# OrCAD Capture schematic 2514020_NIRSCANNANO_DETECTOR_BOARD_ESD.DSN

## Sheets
1 PAGE-01  TITLE: title: ESD, Mobile Spectroscopy Detector Board
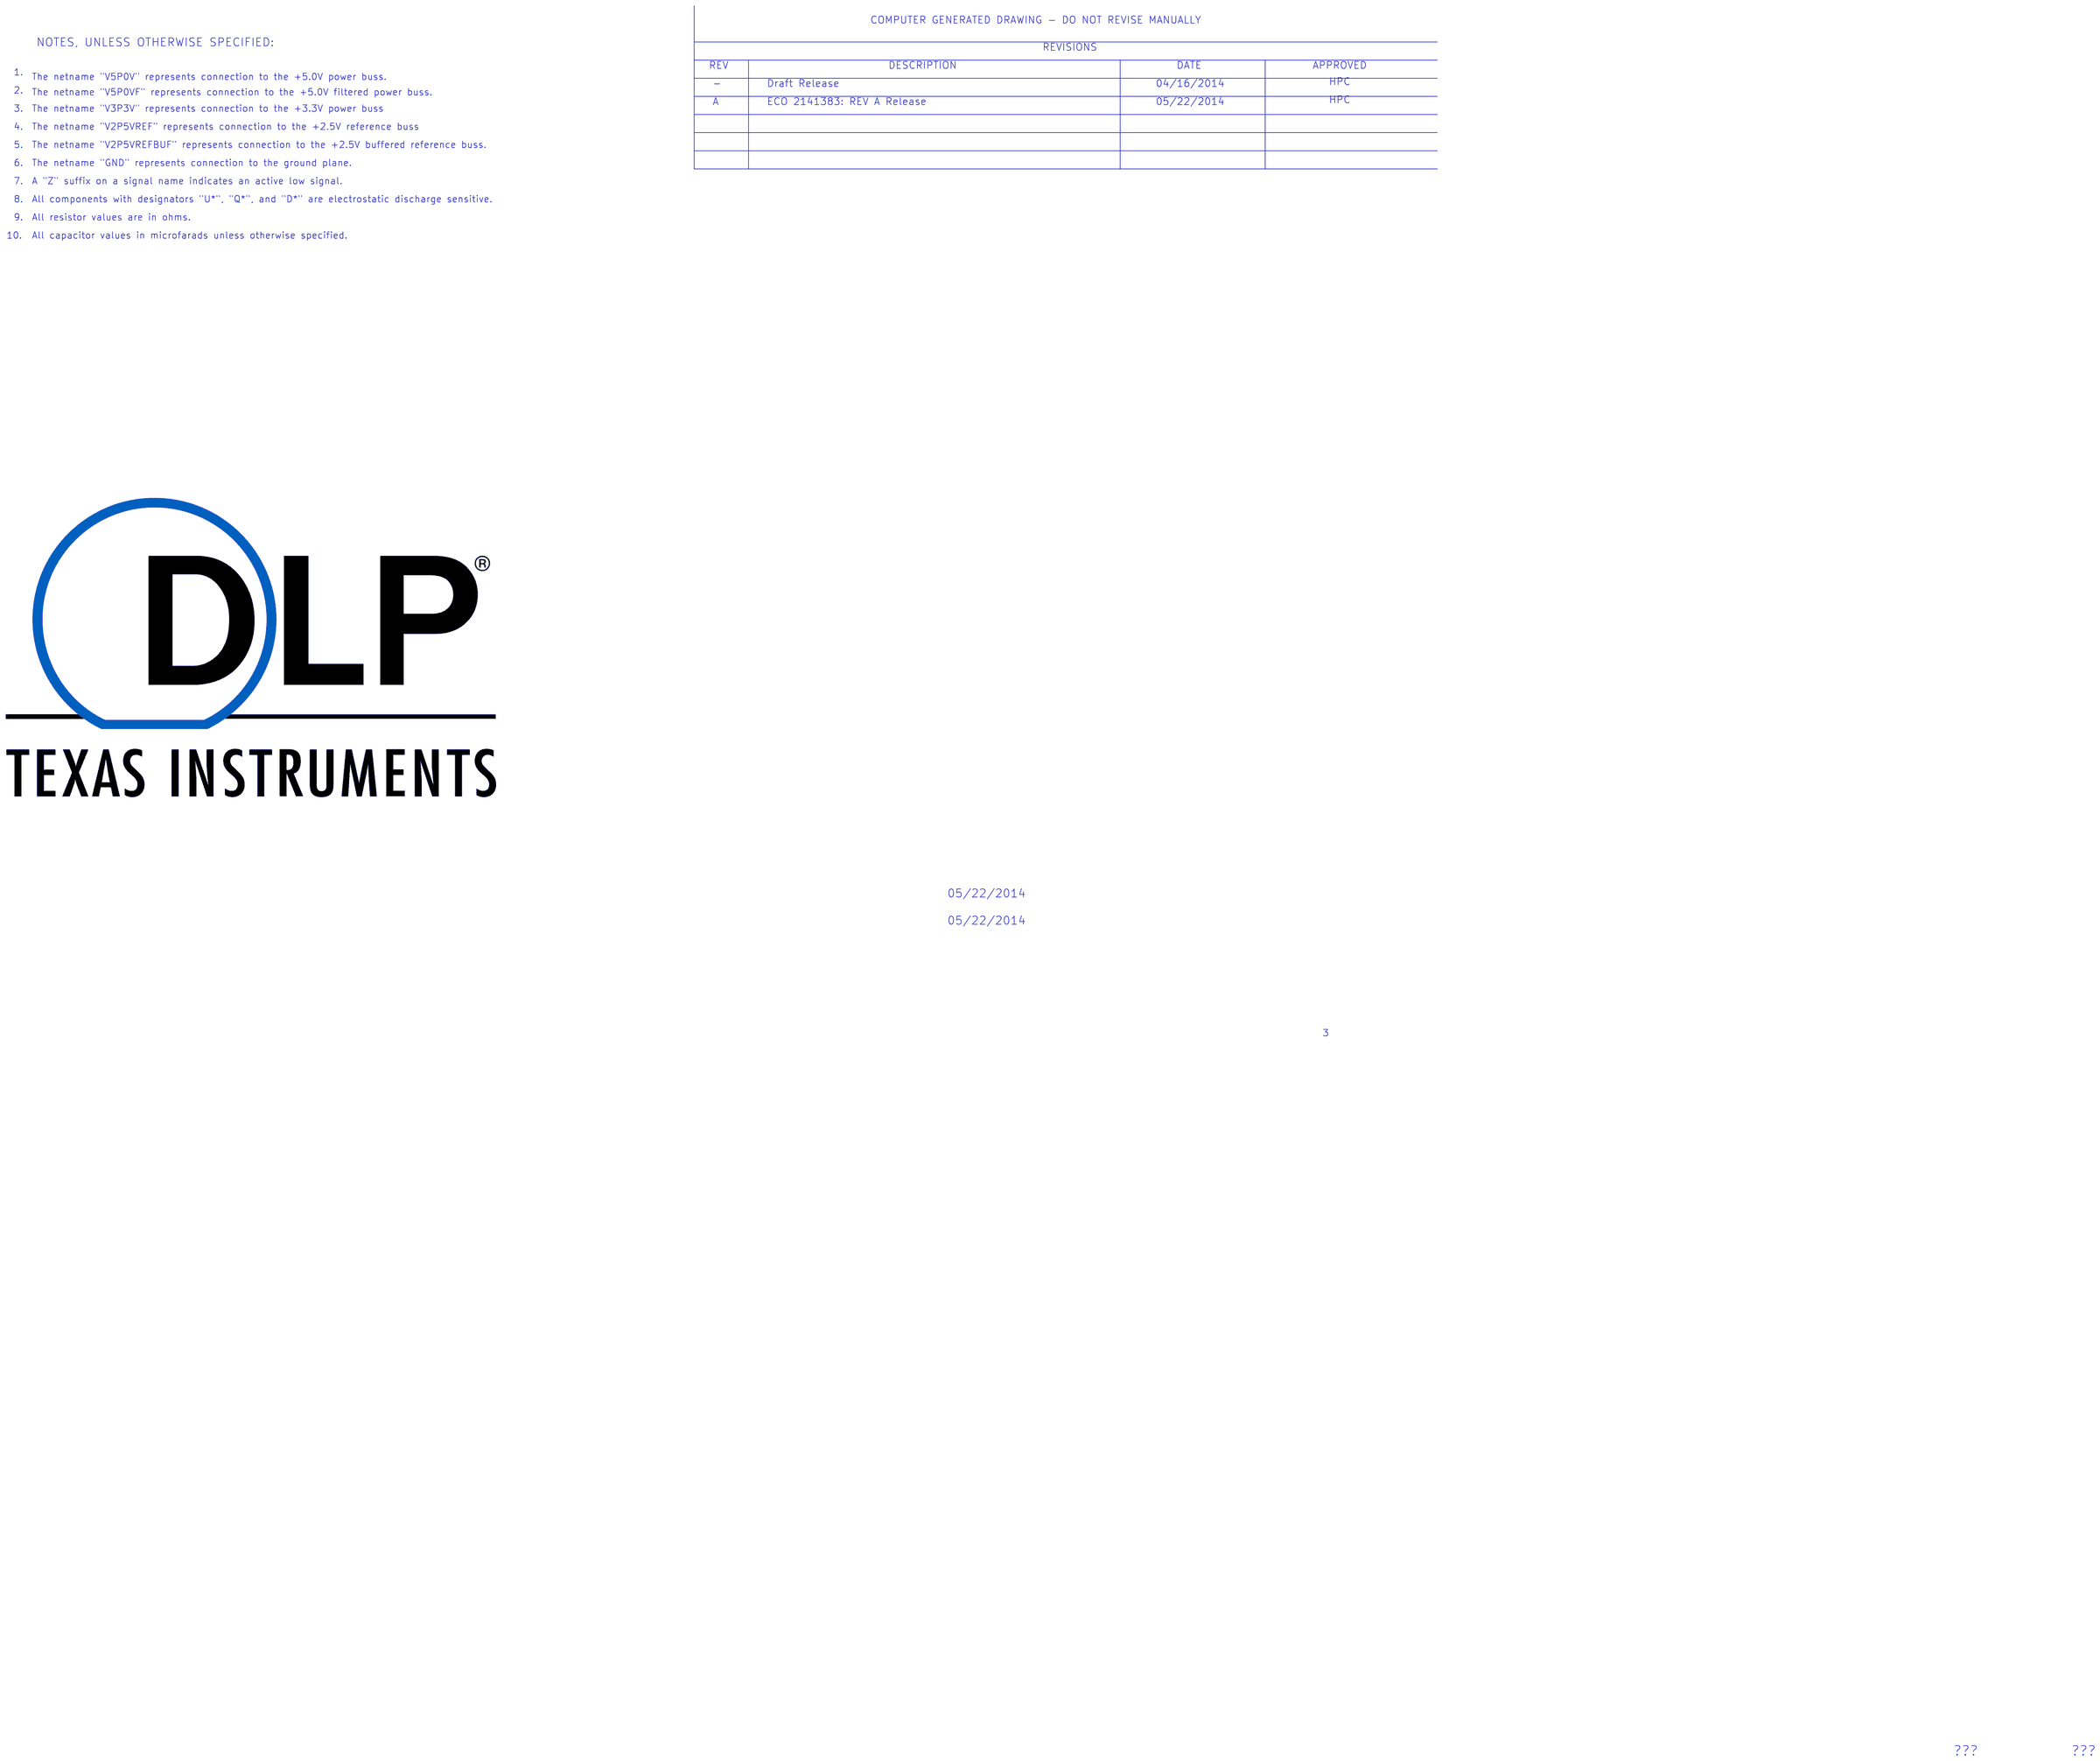
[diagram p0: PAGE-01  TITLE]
2 PAGE-02  Detector Amp ADS1255: size A3
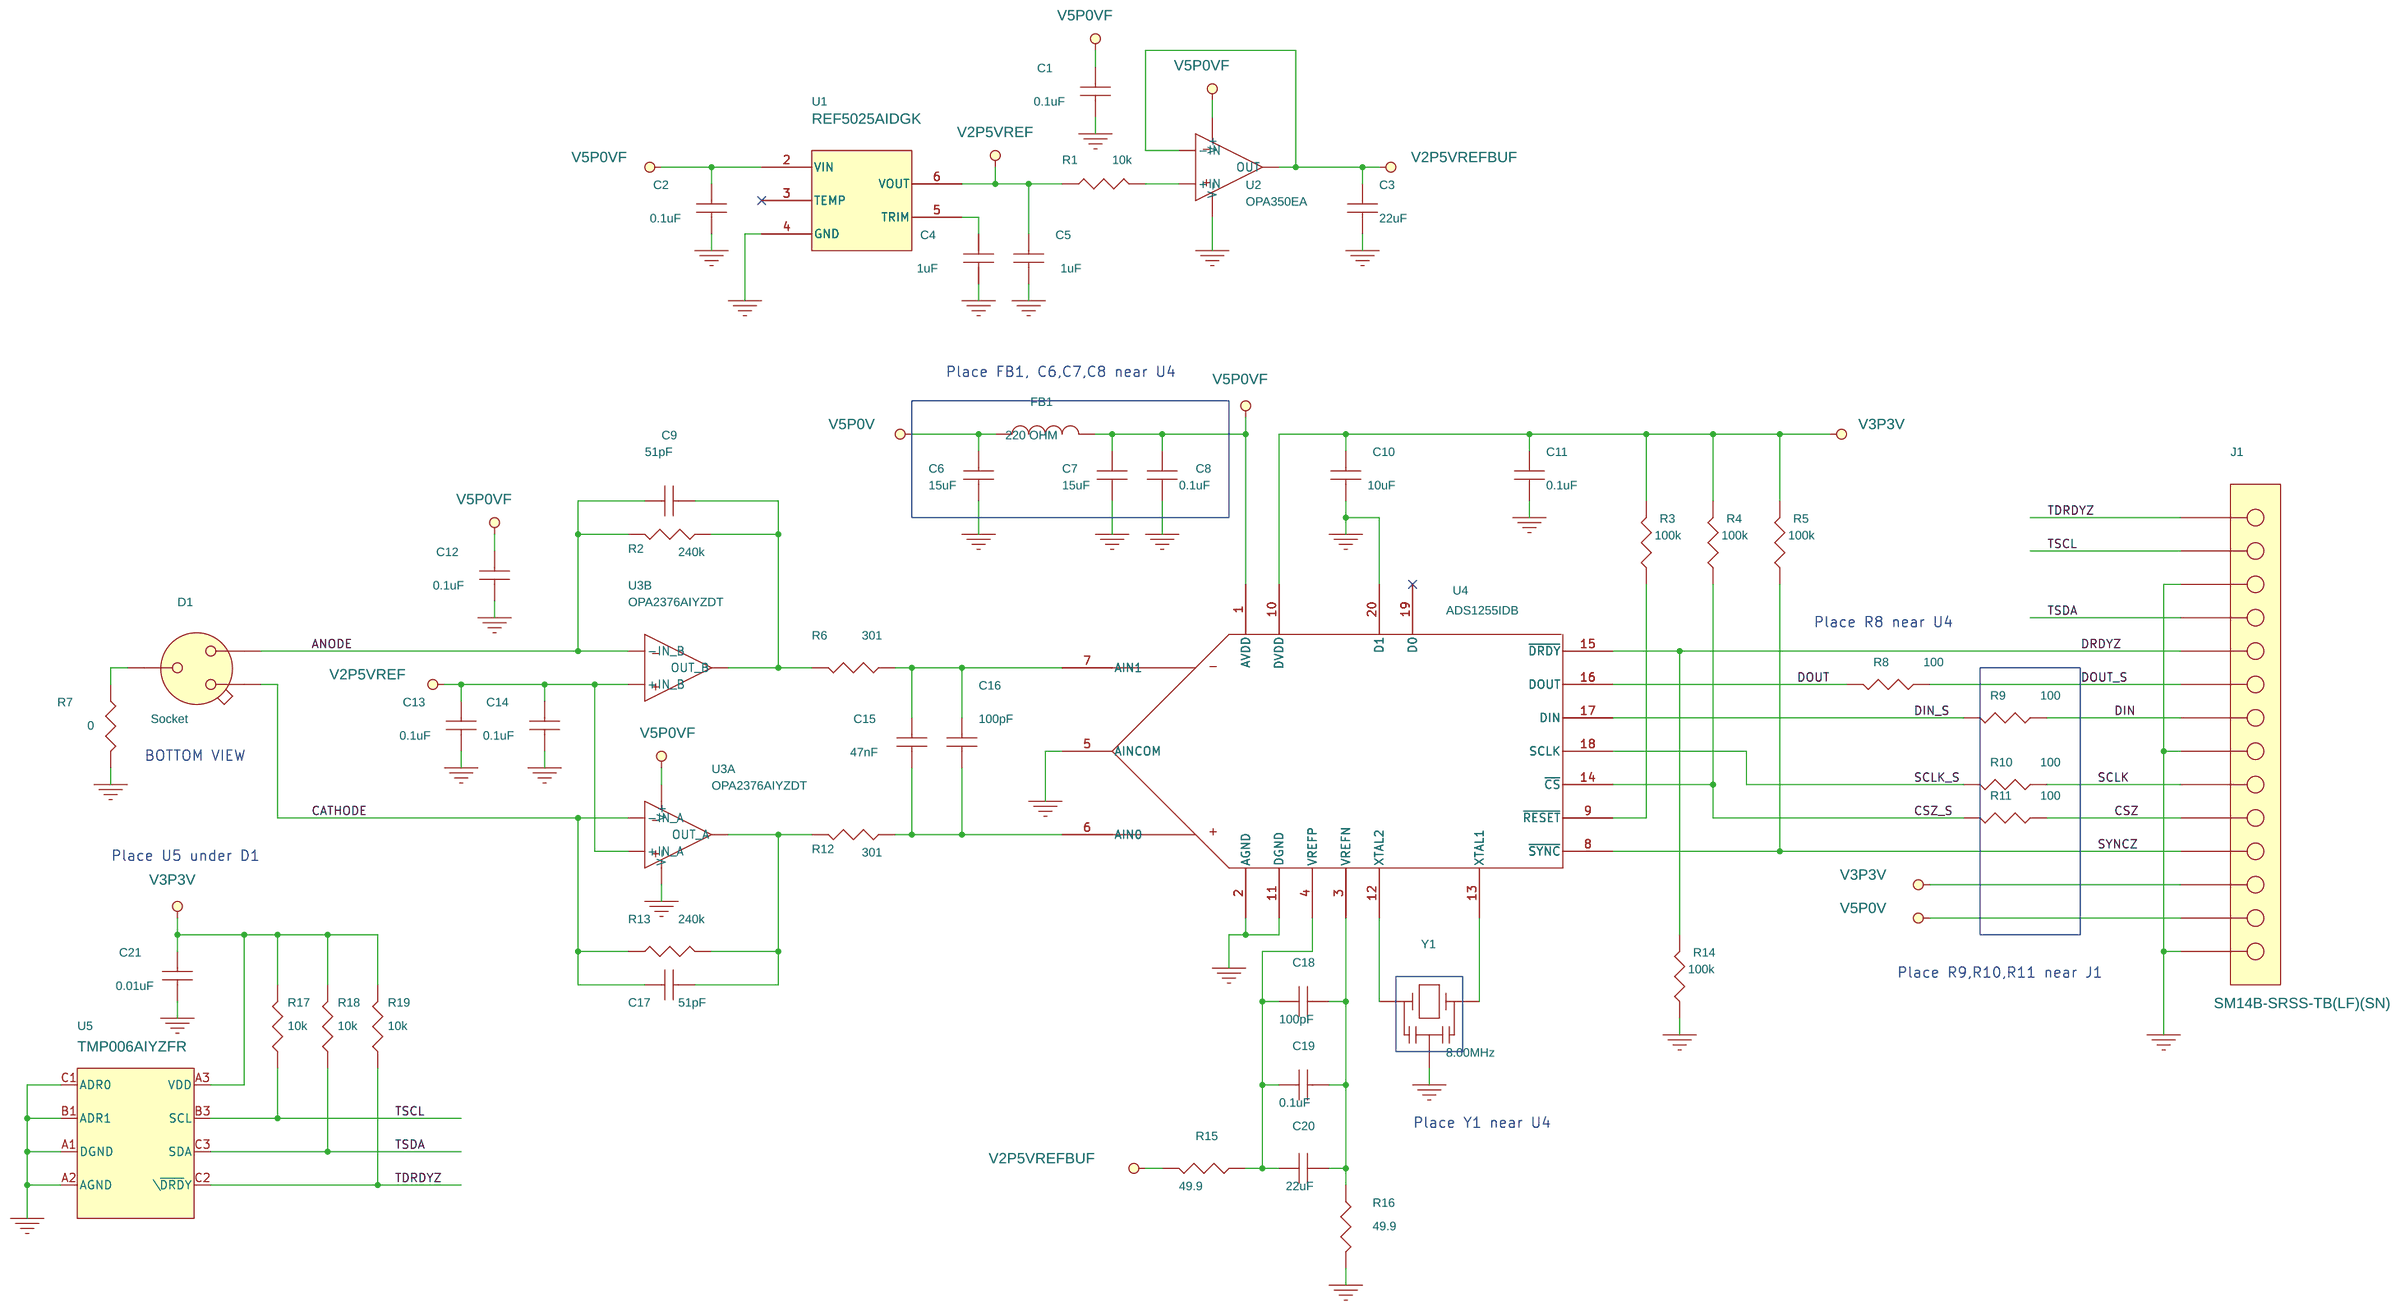
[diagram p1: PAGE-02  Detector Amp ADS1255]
3 PAGE-3  REVISION HISTORY
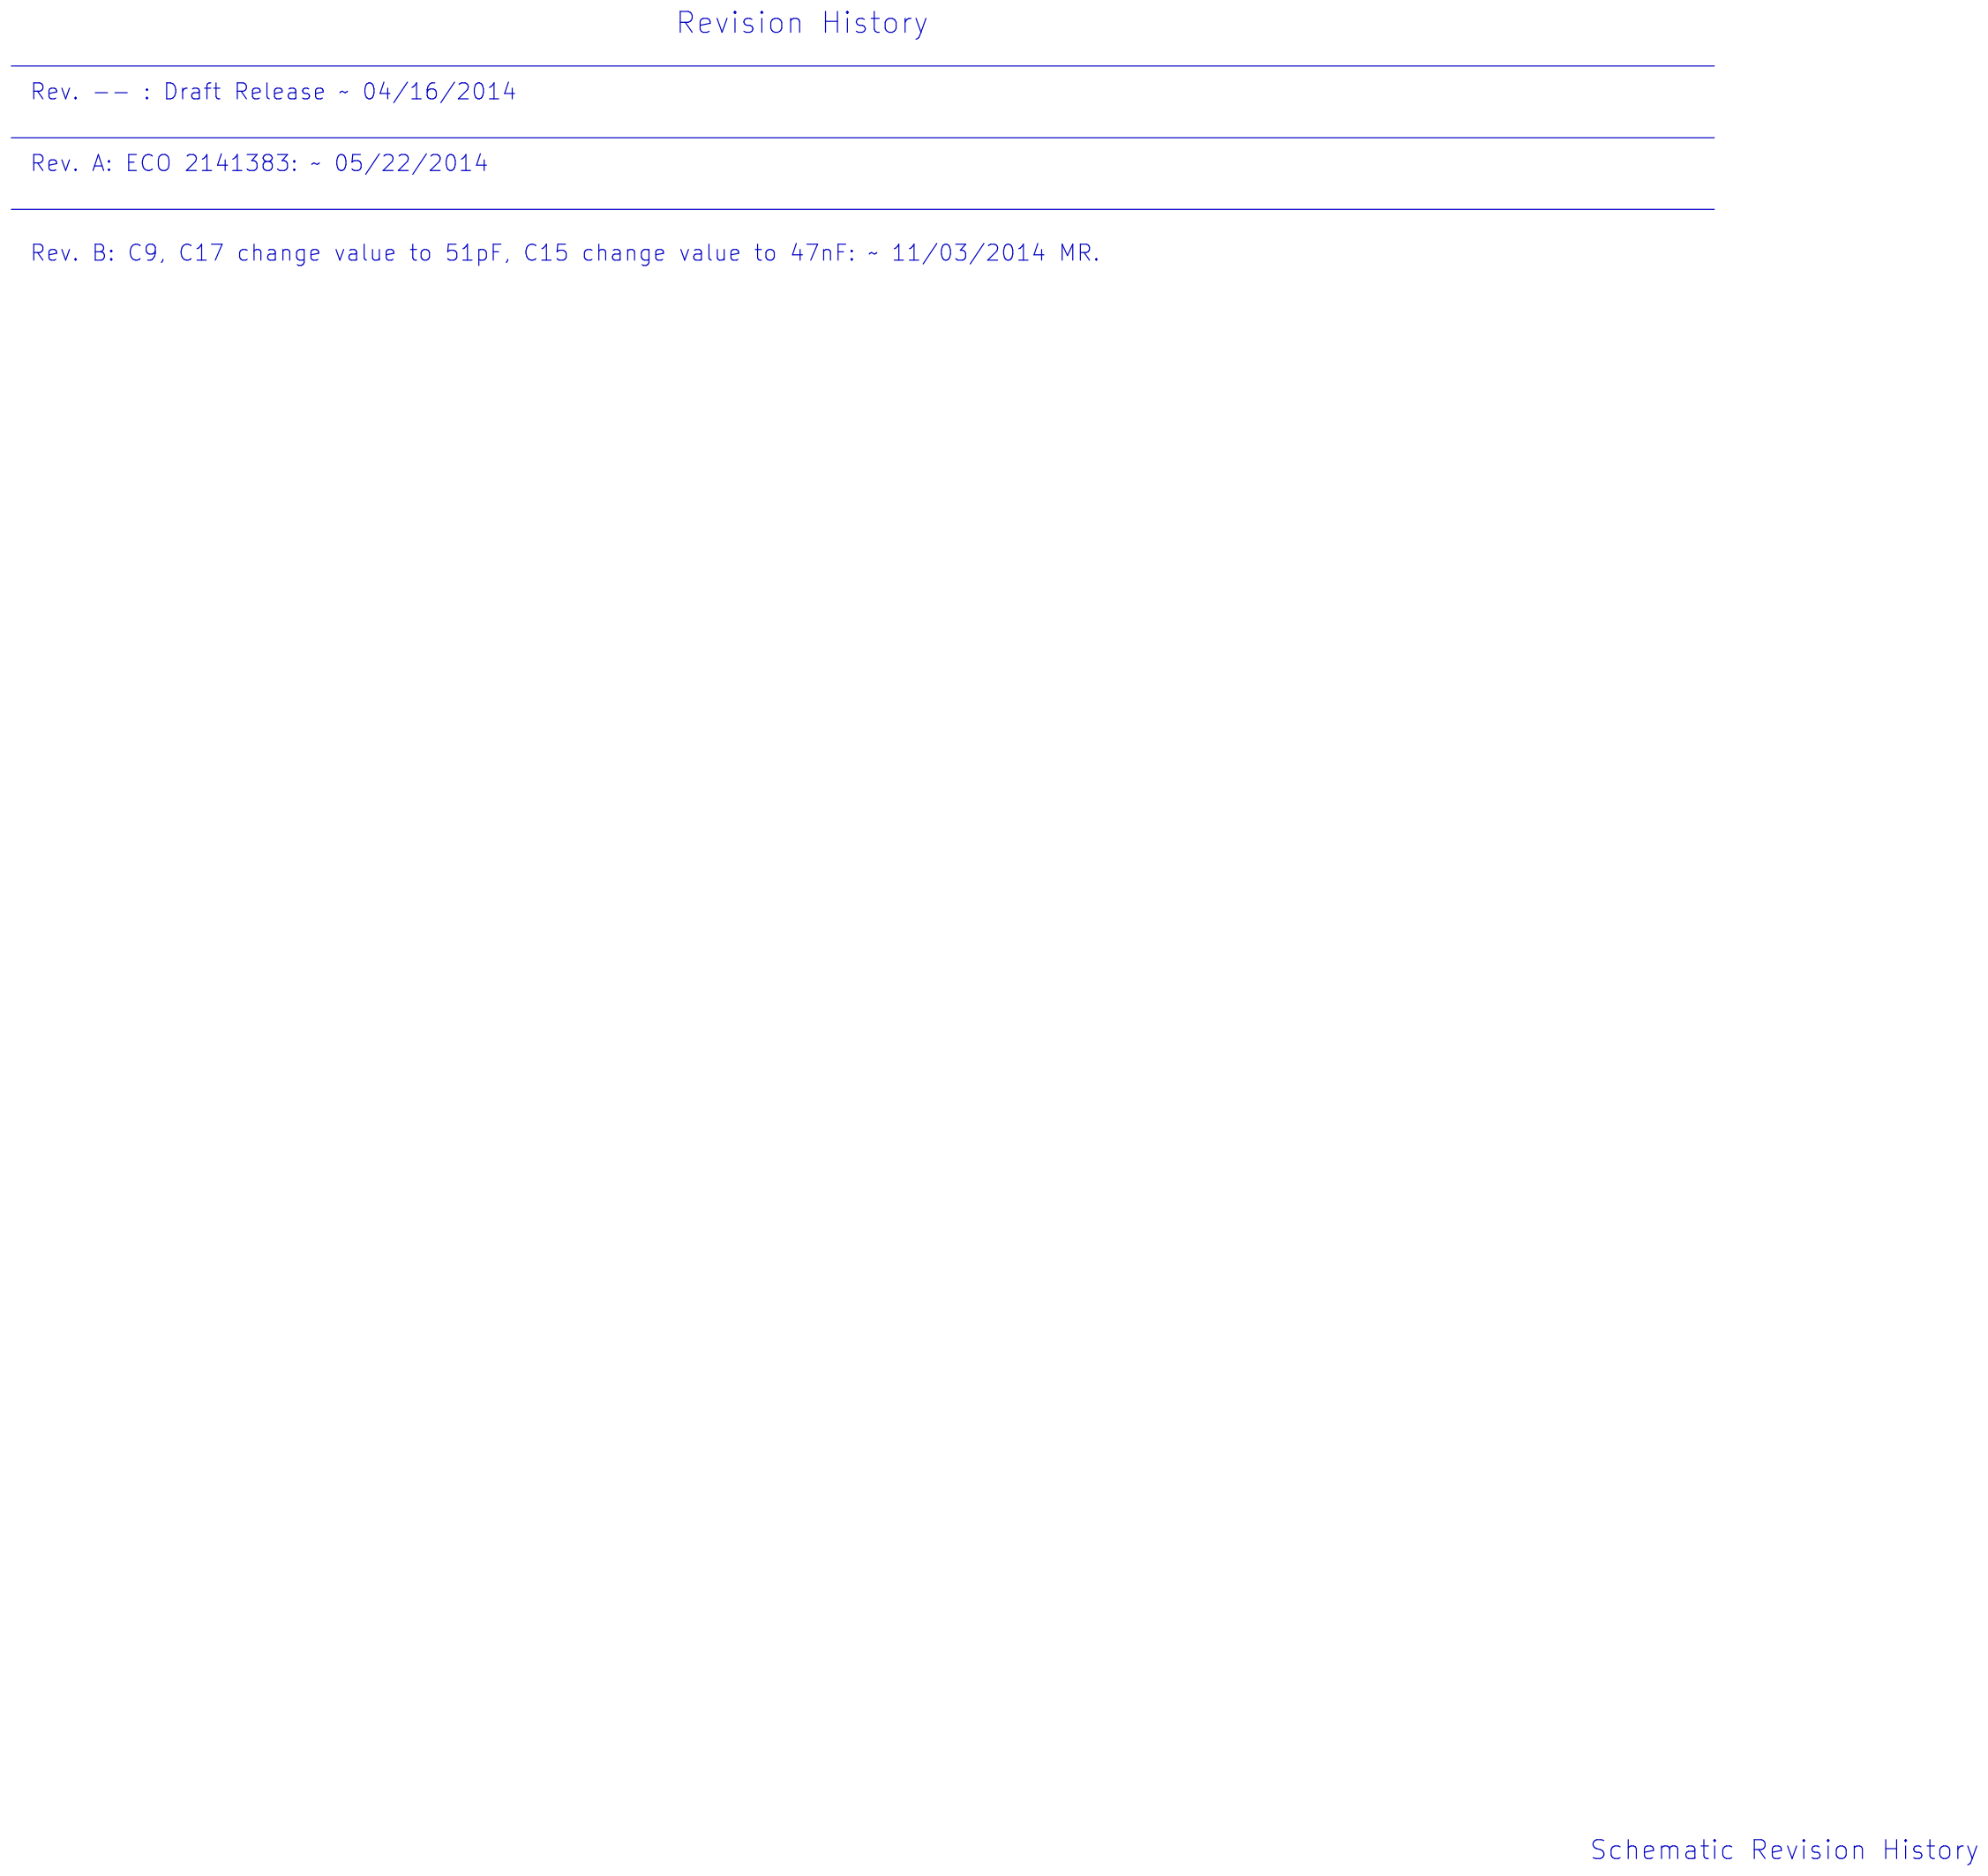
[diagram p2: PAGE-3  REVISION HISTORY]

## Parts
C1  0.1uF  [CAP_0402]
C2  0.1uF  [CAP_0402]
C3  22uF  [CAP_0603]
C4  1uF  [CAP_0603]
C5  1uF  [CAP_0603]
C6  15uF  [CAP_0603]
C7  15uF  [CAP_0603]
C8  0.1uF  [CAP_0402]
C9  51pF  [CAP_0402]
C10  10uF  [CAP_0603]
C11  0.1uF  [CAP_0402]
C12  0.1uF  [CAP_0402]
C13  0.1uF  [CAP_0402]
C14  0.1uF  [CAP_0402]
C15  47nF  [CAP_0402]
C16  100pF  [CAP_0402]
C17  51pF  [CAP_0402]
C18  100pF  [CAP_0402]
C19  0.1uF  [CAP_0402]
C20  22uF  [CAP_0603]
C21  0.01uF  [CAP_0402]
D1  Socket  [SOCKET]
FB1  220 OHM  [FLTR_0402]
J1  SM14B-SRSS-TB(LF)(SN)  [HDR_14_1p0mm]
R1  10k  [RES_0402]
R2  240k  [RES_0402]
R3  100k  [RES_0402]
R4  100k  [RES_0402]
R5  100k  [RES_0402]
R6  301  [RES_0402]
R7  0  [RES_0402]
R8  100  [RES_0402]
R9  100  [RES_0402]
R10  100  [RES_0402]
R11  100  [RES_0402]
R12  301  [RES_0402]
R13  240k  [RES_0402]
R14  100k  [RES_0402]
R15  49.9  [RES_0402]
R16  49.9  [RES_0402]
R17  10k  [RES_0402]
R18  10k  [RES_0402]
R19  10k  [RES_0402]
U1  REF5025AIDGK  [8VSSOP]
U2  OPA350EA  [8VSSOP]
U3  OPA2376AIYZDT  [8DSBGA]  (sections A,B)
U4  ADS1255IDB  [SSOP_20]
U5  TMP006AIYZFR  [8DSBGA]
Y1  8.00MHz  [CEM_RES_CSTCE_G15C]

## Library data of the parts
C1 C2 C8 C12-C14 C19 = CAP_NP: CAP CERAMIC .1UF 25V X5R 0402; MFG: TDK; Manufacturer: TDK; Manufacturer Part Number: C1005X5R1E104K050BC; Part Number: C1005X5R1E104K050BC; RATING: 25V; SOURCE: DIGI 445-4964-1-ND; TOLERANCE: 10%; Type: X5R
C3 C20 = CAP_NP: CAP CERAMIC 22UF 6.3V X5R 0603; MFG: TDK; Manufacturer: TDK; Manufacturer Part Number: C1608X5R0J226M080AC; Part Number: C1608X5R0J226M080AC; RATING: 6.3V; SOURCE: DIGI 445-8028-1-ND; TOLERANCE: 20%; Type: X5R
C4 C5 = CAP_NP: CAP CERAMIC 1UF 10V X5R 0603; MFG: TDK; Manufacturer: TDK; Manufacturer Part Number: C1608X5R1A105K080AC; Part Number: C1608X5R1A105K080AC; RATING: 10V; SOURCE: DIGI 445-1321-1-ND; TOLERANCE: 10%; Type: X5R
C6 C7 = CAP_NP: CAP CER 15UF 10V 20% X5R 0603; MFG: TDK; Manufacturer: TDK; Manufacturer Part Number: C1608X5R1A156M080AC; Part Number: C1608X5R1A156M080AC; RATING: 10V; SOURCE: DIGI 445-9117-1-ND; TOLERANCE: 20%; Type: X5R
C9 = CAP_NP: CAP CERAMIC 51pF 50V X7R 0402; MFG: MuRata; Manufacturer: MuRata; Manufacturer Part Number: GRM1555C1H510JA01D; Part Number: GRM1555C1H510JA01D; RATING: 50V; SOURCE: DIGI 490-5944-1-ND; TOLERANCE: 5%; Type: NPO
C10 = CAP_NP: CAP CERAMIC 10UF 10V X5R 0603; MFG: TDK; Manufacturer: TDK; Manufacturer Part Number: C1608X5R1A106K080AC; Part Number: C1608X5R1A106K080AC; RATING: 10V; SOURCE: DIGI 445-7486-1-ND; TOLERANCE: 10%; Type: X5R
C11 = CAP_NP: CAP CERAMIC .1UF 25V X5R 0402; MFG: TDK; Manufacturer: TDK; Manufacturer Part Number: CC0402KRX5R7BB104; Part Number: C1005X5R1E104K050BC; RATING: 25V; SOURCE: DIGI 445-4964-1-ND; TOLERANCE: 10%; Type: X5R
C15 = CAP_NP: CAP CERAMIC 47nF 25V X5R 0402; MFG: TDK; Manufacturer: MuRata; Manufacturer Part Number: GRM155R71E473KA88D; Part Number: GRM155R71E473KA88D; RATING: 25V; SOURCE: DIGI 490-3254-1-ND; TOLERANCE: 10%; Type: X7R
C16 C18 = CAP_NP: CAP CER 100PF 50V 5% NP0 0402; MFG: TDK; Manufacturer: TDK; Manufacturer Part Number: C1005C0G1H101J050BA; Part Number: C1005C0G1H101J050BA; RATING: 25V; SOURCE: DIGI 445-1247-1-ND; TOLERANCE: 5%; Type: NPO
C17 = CAP_NP: CAP CERAMIC 51pF 50V X7R 0402; MFG: MuRata; Manufacturer: MuRata; Manufacturer Part Number: GRM1555C1H510JA010; Part Number: GRM1555C1H510JA010; RATING: 50V; SOURCE: DIGI 490-5944-1-ND; TOLERANCE: 50%; Type: NPO
C21 = CAP_NP: CAP CER 10000PF 16V 10% X7R 0402; MFG: TDK; Manufacturer: TDK; Manufacturer Part Number: CGJ2B2X7R1C103K050BA; Part Number: CGJ2B2X7R1C103K050BA; RATING: 16V; SOURCE: DIGI 445-8089-1-ND; TOLERANCE: 10%; Type: X7R
D1 = Socket_3_Pin: Socket, Pass Through; Manufacturer: MIILL-MAX; Manufacturer Part Number: 8637-0-15-15-21-27-10-0; Part Number: 8637-0-15-15-21-27-10-0; SOURCE: Mouser_575-8637015152127
FB1 = FERRITE: FERRITE BEAD 220 OHM 0402; MFG: Taiyo Yuden; Manufacturer: Taiyo Yuden; Manufacturer Part Number: BKP1005HS221-T; Part Number: BKP1005HS221-T; RATING: 5A, 100MHz; SOURCE: DIGI 587-2088-1-ND
J1 = CONN_14_1p0mm: CONN HEADR SH 14POS SIDE 1MM TIN; Manufacturer: JST; SOURCE: DIGI 455-1814-1-ND
R1 R17-R19 = 1KR2F: RES 10K OHM 1/16W 1% 0402 SMD; MFG: Yageo; Manufacturer: Yageo; Manufacturer Part Number: RC0402FR-0710KL; Part Number: RC0402FR-0710KL; RATING: 1/16W; SOURCE: DIGI 311-10KLRCT-ND; TOLERANCE: 1%
R2 R13 = 1KR2F: RES 240K OHM 1/16W 1% 0402 SMD; MFG: Yageo; Manufacturer: Yageo; Manufacturer Part Number: RC0402FR-07240KL; Part Number: RC0402FR-07240KL; RATING: 1/16W; SOURCE: DIGI 311-240KLRCT-ND; TOLERANCE: 1%
R3-R5 R14 = R: RES 100K OHM 1/16W 1% 0402 SMD; ICA_MFR_NAME: PANASONIC; ICA_PARTNUM: $$1785048$$ERJ-3GSYJ102; MFG: Yageo; Manufacturer: Yageo; Manufacturer Part Number: RC0402FR-07100KL; Part Number: RC0402FR-07100KL; RATING: 1/10W; SOURCE: DIGI 311-100KLRCT-ND; TOLERANCE: 1%
R6 R12 = 1KR2F: RES 301 OHM 1/16W 1% 0402 SMD; MFG: Yageo; Manufacturer: ROHM; Manufacturer Part Number: RC0402FR-07301RL; Part Number: RC0402FR-07301RL; RATING: 1/16W; SOURCE: DIGI 311-301LRCT-ND; TOLERANCE: 1%
R7 = RES_0_1_16W_1%_0402: RES 0.0 OHM 1/10W JUMP 0402 SMD; Manufacturer: PANASONIC; Part Number: ERJ-2GE0R00X; SOURCE: DIGI P0.0JCT-ND
R8-R11 = 1KR2F: RES 100 OHM 1/16W 1% 0402 SMD; MFG: Yageo; Manufacturer: ROHM; Manufacturer Part Number: MCR01MRTF1000; Part Number: MCR01MRTF1000; RATING: 1/16W; SOURCE: DIGI RHM100CDCT-ND; TOLERANCE: 1%
R15 R16 = 1KR2F: RES 49.9 OHM 1/16W 1% 0402 SMD; MFG: Rohm; Manufacturer: ROHM; Manufacturer Part Number: MCR01MRTF49R9; Part Number: MCR01MRTF49R9; RATING: 1/16W; SOURCE: DIGI RHM49.9CDCT-ND; TOLERANCE: 1%
U1 = REF5025: IC VREF SERIES PREC 2.5V 8VSSOP; Manufacturer: Texas Instruments; SOURCE: DIGI 296-24498-1-ND
U2 = OPA350EA: IC OPAMP GP 38MHZ RRO 8VSSOP; Manufacturer: Texas Instruments; SOURCE: DIGI OPA350EACT-ND
U3 = ANA,OPAMP,OPA2376AIYZDT: IC OPAMP GP 5.5MHZ RRO 8DSBGA; MFG: TEXAS INSTRUMENTS; Manufacturer: TEXAS INSTRUMENTS; SOURCE: DIGI 296-23919-1-ND
U4 = ADS1255IDB_1: IC ADC 24-BIT SPI PROGBL 20-SSOP; MFG: Texas Instruments; Manufacturer: Texas Instruments; SOURCE: DIGI 296-25897-1-ND
U5 = TMP006: IC SENSOR THERMOPILE 8DSBGA; Manufacturer: Texas Instruments; SOURCE: DIGI 296-28819-1-ND
Y1 = RESONATOR: CERAMIC RESONATOR 8.0MHz INTERNAL CAPS; MFG: MURATA; Manufacturer: MURATA; Manufacturer Part Number: CSTCE8M00G52-R0; Part Number: CSTCE8M00G52-R0; SOURCE: DIGI 490-5994-1-ND

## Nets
GND: C1.2 C2.2 C3.2 C4.2 C5.2 C6.2 C7.2 C8.2 C10.2 C11.2 C12.2 C13.2 C14.2 C21.2 J1.1 J1.7 J1.12 R7.1 R14.2 R16.1 U1.4(GND) U2.4(V-) U3.D1(V-) U4.2(AGND) U4.5(AINCOM) U4.11(DGND) U4.20(D1) U5.A1(DGND) U5.A2(AGND) U5.B1(ADR1) U5.C1(ADR0) Y1.2
V2P5VREF: C5.1 C13.1 C14.1 R1.1 U1.6(VOUT) U3.C1(+IN_A) U3.D2(+IN_B)
V2P5VREFBUF: C3.1 R15.1 U2.2(-IN) U2.6(OUT)
V3P3V: C10.1 C11.1 C21.1 J1.3 R3.1 R4.1 R5.1 R17.2 R18.2 R19.2 U4.10(DVDD) U5.A3(VDD)
V5P0V: C6.1 FB1.2 J1.2
V5P0VF: C1.1 C2.1 C7.1 C8.1 C12.1 FB1.1 U1.2(VIN) U2.7(V+) U3.A2(V+) U4.1(AVDD)
ANODE: C9.1 D1.3 R2.1 U3.C2(-IN_B)
CATHODE: C17.1 D1.1 R13.1 U3.B1(-IN_A)
CSZ: J1.5 R11.2
CSZ_S: R4.2 R11.1 U4.14(~{CS})
DIN: J1.8 R9.2
DIN_S: R9.1 U4.17(DIN)
DOUT: R8.1 U4.16(DOUT)
DOUT_S: J1.9 R8.2
DRDYZ: J1.10 R14.1 U4.15(~{DRDY})
SCLK: J1.6 R10.2
SCLK_S: R10.1 U4.18(SCLK)
SYNCZ: J1.4 R5.2 U4.8(~{SYNC})
TDRDYZ: J1.14 R19.1 U5.C2(\~{DRD}Y)
TSCL: J1.13 R17.1 U5.B3(SCL)
TSDA: J1.11 R18.1 U5.C3(SDA)
N41965449: C9.2 R2.2 R6.1 U3.B2(OUT_B)
N41965551: C17.2 R12.1 R13.2 U3.A1(OUT_A)
N41990102: C15.1 C16.1 R6.2 U4.7(AIN1)
N41990105: C15.2 C16.2 R12.2 U4.6(AIN0)
N42023026: C4.1 U1.5(TRIM)
N42087581: C18.1 C19.1 C20.1 R15.2 U4.4(VREFP)
N42087818: C18.2 C19.2 C20.2 R16.2 U4.3(VREFN)
N42088958: U4.12(XTAL2) Y1.1
N42090142: R3.2 U4.9(~{RESET})
N42103947: U4.13(XTAL1) Y1.3
N42120494: R1.2 U2.3(+IN)
N42163672: D1.2 R7.2

Not connected (* = marked no-connect by the designer): U1 3(TEMP)*; U4 19(D0)*

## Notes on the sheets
sheet 1
- COMPUTER GENERATED DRAWING - DO NOT REVISE MANUALLY
- NOTES, UNLESS OTHERWISE SPECIFIED:
- REVISIONS
- REV
- DESCRIPTION
- DATE
- APPROVED
- 1.
- The netname "V5P0V" represents connection to the +5.0V power buss.
- -
- Draft Release
- 04/16/2014
- HPC
- 2.
- The netname "V5P0VF" represents connection to the +5.0V filtered power buss.
- 3.
- The netname "V3P3V" represents connection to the +3.3V power buss
- A
- ECO 2141383: REV A Release
- 05/22/2014
- HPC
- 4.
- The netname "V2P5VREF" represents connection to the +2.5V reference buss
- 5.
- The netname "V2P5VREFBUF" represents connection to the +2.5V buffered reference buss.
- 6.
- The netname "GND" represents connection to the ground plane.
- 7.
- A "Z" suffix on a signal name indicates an active low signal.
- 8.
- All components with designators "U*", "Q*", and "D*" are electrostatic discharge sensitive.
- 9.
- All resistor values are in ohms.
- 10.
- All capacitor values in microfarads unless otherwise specified.
- 05/22/2014
- 05/22/2014
- 3
- ???
- ???
sheet 2
- Place FB1, C6,C7,C8 near U4
- Place R8 near U4
- BOTTOM VIEW
- Place U5 under D1
- Place R9,R10,R11 near J1
- Place Y1 near U4
sheet 3
- Revision History
- Rev. -- : Draft Release ~ 04/16/2014
- Rev. A: ECO 2141383: ~ 05/22/2014
- Rev. B: C9, C17 change value to 51pF, C15 change value to 47nF: ~ 11/03/2014 MR.
- Schematic Revision History
